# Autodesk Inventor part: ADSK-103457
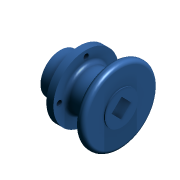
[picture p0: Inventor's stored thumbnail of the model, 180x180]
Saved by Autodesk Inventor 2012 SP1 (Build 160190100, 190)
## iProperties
Shininess: 0.0
Created: 2000-03
Part Number: ADSK-103457
Document SubType Name: Modeling
Stock Number: ADSK-103457
Density: 1 g/cm^3
Material: Default
Density: 0.0
Volume: 0.0
Area: 0.0
PropertySet Name: Model Information
Control State: 0
Checked Out: False
Master: False
Author: gao
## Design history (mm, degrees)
node "Revolution1" dims "d16" = 360 deg
  sketch "Sketch1"
    geometry: L1 (-37.196, -19.878)-(-37.196, -5.59); L2 (-37.196, -5.59)-(-34.196, -5.59); L3 (-34.196, -5.59)-(-34.196, -4.338); L4 (-34.196, -4.338)-(-33.205, -4.338); L5 (-33.205, -4.338)-(-33.205, 22.616); L6 (-33.205, 22.616)-(2.799, 22.616); L7 (2.799, 22.616)-(2.799, 25.122); L8 (2.799, 25.122)-(6.8, 25.122) reference; L9 (6.8, 25.122)-(6.8, 50.122) reference; L10 (6.8, 50.122)-(21.811, 50.122); L11 (21.811, 50.122)-(21.811, 22.104); L12 (21.811, 22.104)-(77.793, 22.104) reference; L13 (77.793, 22.104)-(77.793, 60.119); L14 (77.793, 60.119)-(95.776, 60.119); L15 (95.776, 60.119)-(95.776, 15.752); L16 (95.776, 15.752)-(97.808, 15.752); L17 (97.808, 15.752)-(97.808, 3.378); L18 (-37.196, -19.878)-(97.808, -19.878); L19 (97.808, -19.878)-(97.808, 3.378)
    constraints: 38 end point, 15 parallel, 3 perpendicular, 2 horizontal, 2 vertical
    dimensions: "d0" = 3 distance of L1.end L2.end; "d1" = 0.9906 distance of L3.end L4.end; "d3" = 4.0005 distance of L7.end L8.end; "d4" = 15.0114 distance of L9.end L10.end; "d5" = 17.9832 distance of L13.end L14.end; "d6" = 91.0082 distance between parallel lines of L17 L9; "d7" = 2.032 distance of L15.end L16.end; "d9" = 14.2875 distance of L1.start L1.end; "d11" = 42.4942 distance from line of L1.start L6; "d12" = 69.99986 distance from line of L1.start L10; "d13" = 44.99991 distance from line of L1.start L8; "d14" = 79.9973 distance from line of L14 L1.start; "d15" = 15.5398 distance from line of L18 L4.end; "d50" = 36.0045 distance of L5.end L6.end
node "Fillet1" dims "d17" = 7.9375
node "Hole2" dims "d33" = 11, "d34" = 9.525, "d35" = 6.35, "d36" = 60 deg, "d37" = 25.4, "d38" = 118 deg
  sketch "Sketch4" dims "d32" = 115
    geometry: C1 r 45 at (0, 0) reference; 2 further points
    constraints: 1 coincident, 1 vertical alignment, 2 other
node "Circular Pattern1" dims "d39" = 40, "d41" = 90 deg
workaxis "Work Axis1"
workplane "Work Plane2"
node "Extrusion2" dims "d48" = 22, "d49" = 0
  sketch "Sketch5"
    geometry: L1 (-21.212, 0.21)-(-0.21, -21.212); L2 (-0.21, -21.212)-(21.212, -0.21); L3 (21.212, -0.21)-(0.21, 21.212); L4 (0.21, 21.212)-(-21.212, 0.21); C1 r 35.63 at (0, 0) reference
    constraints: 8 end point, 2 parallel, 1 perpendicular
    dimensions: "d43" = 15 distance from line of L4 C1.centre; "d44" = 30 distance of L1.start L1.end; "d45" = 15 distance from line of L1 C1.centre (= d43); "d47" = 30 distance of L1.end L2.end (= d44)
body "Solid1"
other parameters: "d42" = 45 deg
